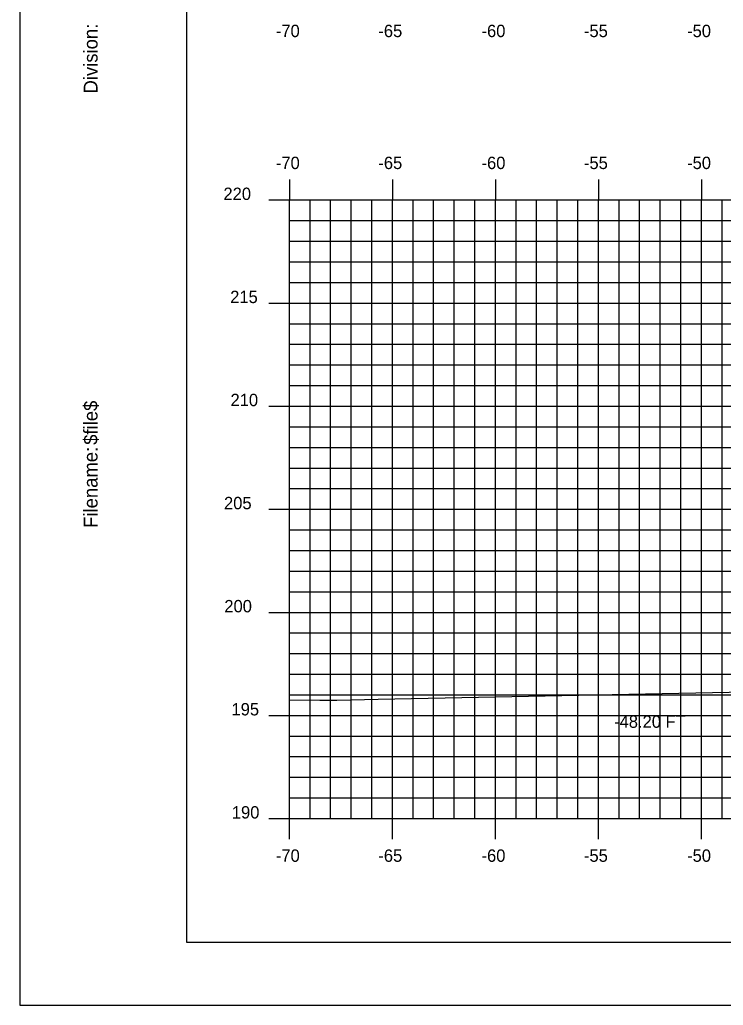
# Model space of a CAD drawing. Extents: x 1138541 to 1138711, y 608981 to 609091.
# Drawn here: x 1138541.34 to 1138575.5, y 608981.28 to 609029.08 of the extents above; entities that cross this region are included whole.
import ezdxf

# ---------------------------------------------------------------- set-up
doc = ezdxf.new("R2010")
doc.units = 0
for name, color, linetype in [('BORDER', 7, 'Continuous'), ('D_Text_Standard', 7, 'Continuous'), ('H_V ANNOTATION', 7, 'Continuous'), ('MAJOR', 7, 'Continuous'), ('MINOR', 7, 'Continuous'), ('PLOT BOUNDARY', 7, 'Continuous'), ('S_Roadway_Centerline', 7, 'Continuous')]:
    doc.layers.add(name, color=color, linetype=linetype)

msp = doc.modelspace()

# ---------------------------------------------------------------- linework, layer by layer
at = {"layer": 'BORDER'}
msp.add_lwpolyline([(1138549.436, 608984.335), (1138709.436, 608984.335), (1138709.436, 609089.335), (1138549.436, 609089.335)], close=True, dxfattribs=at)
at = {"layer": 'MAJOR'}
for p, q in [((1138554.436, 609021.337), (1138554.436, 609020.335)), ((1138559.436, 609021.337), (1138559.436, 609020.335)), ((1138564.436, 609021.337), (1138564.436, 609020.335)), ((1138569.436, 609021.337), (1138569.436, 609020.335)), ((1138574.436, 609021.337), (1138574.436, 609020.335)), ((1138553.434, 609020.335), (1138554.436, 609020.335)), ((1138554.436, 609020.335), (1138694.436, 609020.335)), ((1138554.436, 608990.335), (1138554.436, 609020.335)), ((1138554.436, 608990.335), (1138554.436, 609020.335)), ((1138554.436, 609020.335), (1138694.436, 609020.335)), ((1138559.436, 608990.335), (1138559.436, 609020.335)), ((1138564.436, 608990.335), (1138564.436, 609020.335)), ((1138569.436, 608990.335), (1138569.436, 609020.335)), ((1138574.436, 608990.335), (1138574.436, 609020.335)), ((1138553.434, 609015.335), (1138554.436, 609015.335)), ((1138554.436, 609015.335), (1138694.436, 609015.335)), ((1138553.434, 609010.335), (1138554.436, 609010.335)), ((1138554.436, 609010.335), (1138694.436, 609010.335)), ((1138553.434, 609005.335), (1138554.436, 609005.335)), ((1138554.436, 609005.335), (1138694.436, 609005.335)), ((1138553.434, 609000.335), (1138554.436, 609000.335)), ((1138554.436, 609000.335), (1138694.436, 609000.335)), ((1138553.434, 608995.335), (1138554.436, 608995.335)), ((1138554.436, 608995.335), (1138694.436, 608995.335)), ((1138553.434, 608990.335), (1138554.436, 608990.335)), ((1138554.436, 608990.335), (1138694.436, 608990.335)), ((1138554.436, 608990.335), (1138694.436, 608990.335)), ((1138554.436, 608989.333), (1138554.436, 608990.335)), ((1138559.436, 608989.333), (1138559.436, 608990.335)), ((1138564.436, 608989.333), (1138564.436, 608990.335)), ((1138569.436, 608989.333), (1138569.436, 608990.335)), ((1138574.436, 608989.333), (1138574.436, 608990.335))]:
    msp.add_line(p, q, dxfattribs=at)
at = {"layer": 'MINOR'}
for p, q in [((1138555.436, 608990.335), (1138555.436, 609020.335)), ((1138556.436, 608990.335), (1138556.436, 609020.335)), ((1138557.436, 608990.335), (1138557.436, 609020.335)), ((1138558.436, 608990.335), (1138558.436, 609020.335)), ((1138560.436, 608990.335), (1138560.436, 609020.335)), ((1138561.436, 608990.335), (1138561.436, 609020.335)), ((1138562.436, 608990.335), (1138562.436, 609020.335)), ((1138563.436, 608990.335), (1138563.436, 609020.335)), ((1138565.436, 608990.335), (1138565.436, 609020.335)), ((1138566.436, 608990.335), (1138566.436, 609020.335)), ((1138567.436, 608990.335), (1138567.436, 609020.335)), ((1138568.436, 608990.335), (1138568.436, 609020.335)), ((1138570.436, 608990.335), (1138570.436, 609020.335)), ((1138571.436, 608990.335), (1138571.436, 609020.335)), ((1138572.436, 608990.335), (1138572.436, 609020.335)), ((1138573.436, 608990.335), (1138573.436, 609020.335)), ((1138575.436, 608990.335), (1138575.436, 609020.335)), ((1138554.436, 609019.335), (1138694.436, 609019.335)), ((1138554.436, 609019.335), (1138555.438, 609019.335)), ((1138554.436, 609018.335), (1138694.436, 609018.335)), ((1138554.436, 609018.335), (1138555.438, 609018.335)), ((1138554.436, 609017.335), (1138694.436, 609017.335)), ((1138554.436, 609017.335), (1138555.438, 609017.335)), ((1138554.436, 609016.335), (1138694.436, 609016.335)), ((1138554.436, 609016.335), (1138555.438, 609016.335)), ((1138554.436, 609014.335), (1138694.436, 609014.335)), ((1138554.436, 609014.335), (1138555.438, 609014.335)), ((1138554.436, 609013.335), (1138694.436, 609013.335)), ((1138554.436, 609013.335), (1138555.438, 609013.335)), ((1138554.436, 609012.335), (1138694.436, 609012.335)), ((1138554.436, 609012.335), (1138555.438, 609012.335)), ((1138554.436, 609011.335), (1138694.436, 609011.335)), ((1138554.436, 609011.335), (1138555.438, 609011.335)), ((1138554.436, 609009.335), (1138694.436, 609009.335)), ((1138554.436, 609009.335), (1138555.438, 609009.335)), ((1138554.436, 609008.335), (1138694.436, 609008.335)), ((1138554.436, 609008.335), (1138555.438, 609008.335)), ((1138554.436, 609007.335), (1138694.436, 609007.335)), ((1138554.436, 609007.335), (1138555.438, 609007.335)), ((1138554.436, 609006.335), (1138694.436, 609006.335)), ((1138554.436, 609006.335), (1138555.438, 609006.335)), ((1138554.436, 609004.335), (1138694.436, 609004.335)), ((1138554.436, 609004.335), (1138555.438, 609004.335)), ((1138554.436, 609003.335), (1138694.436, 609003.335)), ((1138554.436, 609003.335), (1138555.438, 609003.335)), ((1138554.436, 609002.335), (1138694.436, 609002.335)), ((1138554.436, 609002.335), (1138555.438, 609002.335)), ((1138554.436, 609001.335), (1138694.436, 609001.335)), ((1138554.436, 609001.335), (1138555.438, 609001.335)), ((1138554.436, 608999.335), (1138694.436, 608999.335)), ((1138554.436, 608999.335), (1138555.438, 608999.335)), ((1138554.436, 608998.335), (1138694.436, 608998.335)), ((1138554.436, 608998.335), (1138555.438, 608998.335)), ((1138554.436, 608997.335), (1138694.436, 608997.335)), ((1138554.436, 608997.335), (1138555.438, 608997.335)), ((1138554.436, 608996.335), (1138694.436, 608996.335)), ((1138554.436, 608996.335), (1138555.438, 608996.335)), ((1138554.436, 608994.335), (1138694.436, 608994.335)), ((1138554.436, 608994.335), (1138555.438, 608994.335)), ((1138554.436, 608993.335), (1138694.436, 608993.335)), ((1138554.436, 608993.335), (1138555.438, 608993.335)), ((1138554.436, 608992.335), (1138694.436, 608992.335)), ((1138554.436, 608992.335), (1138555.438, 608992.335)), ((1138554.436, 608991.335), (1138694.436, 608991.335)), ((1138554.436, 608991.335), (1138555.438, 608991.335))]:
    msp.add_line(p, q, dxfattribs=at)
at = {"layer": 'PLOT BOUNDARY'}
msp.add_lwpolyline([(1138541.342, 608981.276), (1138711.342, 608981.276), (1138711.342, 609091.276), (1138541.342, 609091.276)], close=True, dxfattribs=at)
at = {"layer": 'S_Roadway_Centerline'}
msp.add_lwpolyline([(1138554.436, 608996.093), (1138555.914, 608996.078), (1138556.733, 608996.072), (1138558.742, 608996.121), (1138576.588, 608996.487), (1138577.586, 608996.79), (1138580.96, 608997.947), (1138584.879, 609000.024), (1138599.606, 609007.341), (1138602.407, 609008.555), (1138609.669, 609012.124), (1138611.981, 609012.675), (1138613.716, 609012.981), (1138623.446, 609013.107), (1138624.559, 609013.121), (1138634.558, 609012.938), (1138635.398, 609012.927), (1138635.681, 609012.919), (1138638.229, 609012.472), (1138646.037, 609008.404)], dxfattribs=at)

# ---------------------------------------------------------------- texts
at = {"layer": 'BORDER'}
for s, p in [('Division:', (1138545.121, 609025.501)), ('$file$', (1138545.121, 609008.461)), ('Filename:', (1138545.121, 609004.433))]:
    msp.add_text(s, height=0.6696, rotation=90, dxfattribs=at).set_placement(p)
at = {"layer": 'D_Text_Standard'}
msp.add_text('-48.20 FT', height=0.6, dxfattribs=at).set_placement((1138570.197, 608994.734))
at = {"layer": 'H_V ANNOTATION'}
for s, p in [('-70', (1138553.777, 609028.235)), ('-65', (1138558.753, 609028.235)), ('-60', (1138563.761, 609028.235)), ('-55', (1138568.732, 609028.235)), ('-50', (1138573.74, 609028.235)), ('-70', (1138553.777, 609021.835)), ('-65', (1138558.753, 609021.835)), ('-60', (1138563.761, 609021.835)), ('-55', (1138568.732, 609021.835)), ('-50', (1138573.74, 609021.835)), ('220', (1138551.233, 609020.335)), ('215', (1138551.56, 609015.335)), ('210', (1138551.576, 609010.335)), ('205', (1138551.26, 609005.335)), ('200', (1138551.276, 609000.335)), ('195', (1138551.624, 608995.335)), ('190', (1138551.64, 608990.335)), ('-70', (1138553.777, 608988.235)), ('-65', (1138558.753, 608988.235)), ('-60', (1138563.761, 608988.235)), ('-55', (1138568.732, 608988.235)), ('-50', (1138573.74, 608988.235))]:
    msp.add_text(s, height=0.6, dxfattribs=at).set_placement(p)
at = {"layer": 'MAJOR'}
msp.add_text('-', height=0.006, dxfattribs=at).set_placement((1138554.431, 608990.335))

doc.saveas('drawing.dxf')
